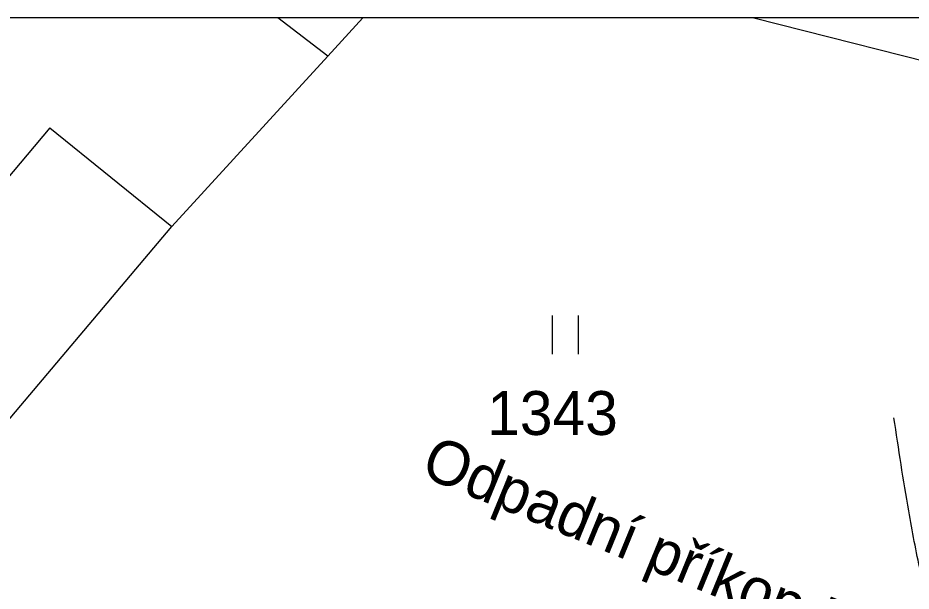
# Model space of a CAD drawing. Extents: x -564037 to -563827, y -1163561 to -1163412.
# Drawn here: x -564012.13 to -563977.56, y -1163434.68 to -1163412.49 of the extents above; entities that cross this region are included whole.
import ezdxf

# ---------------------------------------------------------------- set-up
doc = ezdxf.new("R2010")
doc.units = 0
for name, color, linetype in [('4', 7, 'Continuous'), ('_rám RT1', 7, 'Continuous'), ('Hranice parcel', 7, 'Continuous'), ('Parcelní čísla', 7, 'Continuous'), ('Vnitřní kresba', 7, 'Continuous'), ('Vrstva 25', 7, 'Continuous'), ('Značky kultur', 7, 'Continuous')]:
    doc.layers.add(name, color=color, linetype=linetype)

msp = doc.modelspace()

# ---------------------------------------------------------------- linework, layer by layer
at = {"layer": '_rám RT1'}
msp.add_line((-563826.505, -1163412.494), (-564036.505, -1163412.494), dxfattribs=at)
at = {"layer": 'Hranice parcel'}
msp.add_line((-564000.13, -1163413.97), (-563998.781, -1163412.494), dxfattribs=at)
for points in [[(-564000.13, -1163413.97), (-564002.064, -1163412.494)], [(-563983.645, -1163412.494), (-563974.99, -1163414.69), (-563964.47, -1163416.08)], [(-564025.34, -1163443.25), (-564021.14, -1163438.29), (-564006.17, -1163420.57), (-564000.13, -1163413.97)]]:
    msp.add_lwpolyline(points, dxfattribs=at)
at = {"layer": 'Vnitřní kresba'}
for q in [(-564025.9, -1163434.51), (-564006.17, -1163420.57)]:
    msp.add_line((-564010.89, -1163416.75), q, dxfattribs=at)
at = {"layer": 'Vrstva 25'}
msp.add_spline([(-563963.083, -1163462.145), (-563963.39, -1163461.716), (-563965.099, -1163459.374), (-563968.902, -1163454.148), (-563969.809, -1163452.732), (-563970.748, -1163451.061), (-563971.513, -1163449.395), (-563972.793, -1163446.36), (-563973.096, -1163445.688), (-563973.41, -1163445.02), (-563973.725, -1163444.353), (-563974.033, -1163443.682), (-563975.446, -1163440.197), (-563976.63, -1163436.253), (-563976.917, -1163435.088), (-563977.191, -1163433.921), (-563977.649, -1163431.571), (-563978.22, -1163427.97)], degree=3, dxfattribs=at)
at = {"layer": 'Značky kultur'}
for p, q in [((-563991.431, -1163425.51), (-563991.431, -1163424.01)), ((-563990.43, -1163425.51), (-563990.43, -1163424.01))]:
    msp.add_line(p, q, dxfattribs=at)

# ---------------------------------------------------------------- texts
at = {"layer": '4'}
msp.add_text('Odpadní příkop PRI1', height=1.70472, rotation=337.7031, dxfattribs=at).set_placement((-563996.602, -1163430.187))
at = {"layer": 'Parcelní čísla'}
msp.add_text('1343', height=1.7, dxfattribs=at).set_placement((-563993.964, -1163428.634))

doc.saveas('drawing.dxf')
